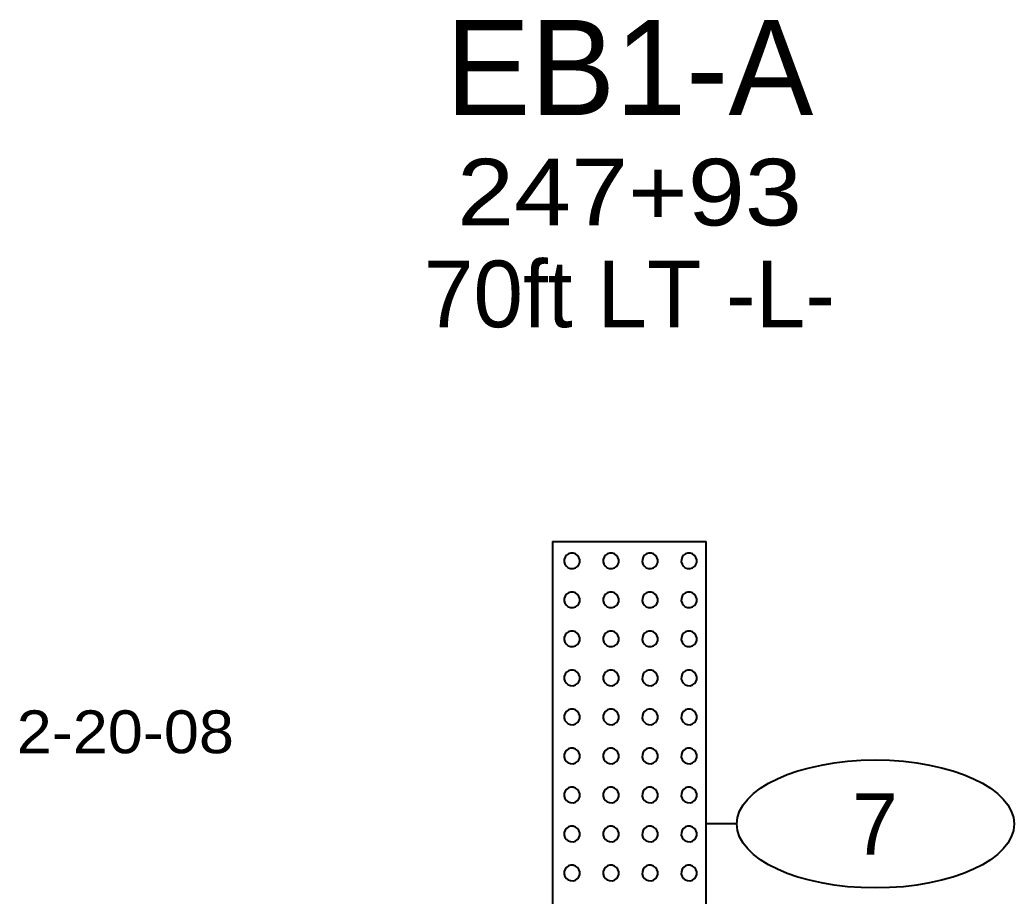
# Model space of a CAD drawing. Extents: x -76 to 974, y -1080 to -735.
# Drawn here: x -75.83 to -59.64, y -772.48 to -758.22 of the extents above; entities that cross this region are included whole.
import ezdxf
from ezdxf.enums import TextEntityAlignment as Align

# ---------------------------------------------------------------- set-up
doc = ezdxf.new("R2010")
doc.units = 0
doc.header["$LTSCALE"] = 0.36
doc.layers.add('27', color=7, linetype='Continuous', lineweight=40)

msp = doc.modelspace()

# ---------------------------------------------------------------- linework, layer by layer
at = {"layer": '27'}
for p, q in [((-67.154, -766.7053), (-67.154, -778.2053)), ((-67.154, -766.7053), (-64.654, -766.7053)), ((-64.654, -778.2053), (-64.654, -766.7053)), ((-64.154, -771.3053), (-64.654, -771.3053))]:
    msp.add_line(p, q, dxfattribs=at)
for points in [[(-66.7094, -767.0228), (-66.7109, -767.003), (-66.7231, -766.9654), (-66.7462, -766.9333), (-66.7781, -766.9099), (-66.8156, -766.8974), (-66.8552, -766.8971), (-66.8929, -766.9089), (-66.9252, -766.9317), (-66.9489, -766.9634), (-66.9617, -767.0008), (-66.9624, -767.0404), (-66.9509, -767.0782), (-66.9283, -767.1107), (-66.8969, -767.1347), (-66.8595, -767.1478), (-66.82, -767.1489), (-66.7821, -767.1377), (-66.7494, -767.1154), (-66.7251, -767.0841), (-66.7117, -767.0469)], [(-66.0744, -767.0228), (-66.0759, -767.003), (-66.0881, -766.9654), (-66.1112, -766.9333), (-66.1431, -766.9099), (-66.1806, -766.8974), (-66.2202, -766.8971), (-66.2579, -766.9089), (-66.2902, -766.9317), (-66.3139, -766.9634), (-66.3267, -767.0008), (-66.3274, -767.0404), (-66.3159, -767.0782), (-66.2933, -767.1107), (-66.2619, -767.1347), (-66.2245, -767.1478), (-66.185, -767.1489), (-66.1471, -767.1377), (-66.1144, -767.1154), (-66.0901, -767.0841), (-66.0767, -767.0469)], [(-65.4394, -767.0228), (-65.4409, -767.003), (-65.4531, -766.9654), (-65.4762, -766.9333), (-65.5081, -766.9099), (-65.5456, -766.8974), (-65.5852, -766.8971), (-65.6229, -766.9089), (-65.6552, -766.9317), (-65.6789, -766.9634), (-65.6917, -767.0008), (-65.6924, -767.0404), (-65.6809, -767.0782), (-65.6583, -767.1107), (-65.6269, -767.1347), (-65.5895, -767.1478), (-65.55, -767.1489), (-65.5121, -767.1377), (-65.4794, -767.1154), (-65.4551, -767.0841), (-65.4417, -767.0469)], [(-64.8044, -767.0228), (-64.8059, -767.003), (-64.8181, -766.9654), (-64.8412, -766.9333), (-64.8731, -766.9099), (-64.9106, -766.8974), (-64.9502, -766.8971), (-64.9879, -766.9089), (-65.0202, -766.9317), (-65.0439, -766.9634), (-65.0567, -767.0008), (-65.0574, -767.0404), (-65.0459, -767.0782), (-65.0233, -767.1107), (-64.9919, -767.1347), (-64.9545, -767.1478), (-64.915, -767.1489), (-64.8771, -767.1377), (-64.8444, -767.1154), (-64.8201, -767.0841), (-64.8067, -767.0469)], [(-66.7094, -767.6578), (-66.7109, -767.638), (-66.7231, -767.6004), (-66.7462, -767.5683), (-66.7781, -767.5449), (-66.8156, -767.5324), (-66.8552, -767.5321), (-66.8929, -767.5439), (-66.9252, -767.5667), (-66.9489, -767.5984), (-66.9617, -767.6358), (-66.9624, -767.6754), (-66.9509, -767.7132), (-66.9283, -767.7457), (-66.8969, -767.7697), (-66.8595, -767.7828), (-66.82, -767.7839), (-66.7821, -767.7727), (-66.7494, -767.7504), (-66.7251, -767.7191), (-66.7117, -767.6819)], [(-66.0744, -767.6578), (-66.0759, -767.638), (-66.0881, -767.6004), (-66.1112, -767.5683), (-66.1431, -767.5449), (-66.1806, -767.5324), (-66.2202, -767.5321), (-66.2579, -767.5439), (-66.2902, -767.5667), (-66.3139, -767.5984), (-66.3267, -767.6358), (-66.3274, -767.6754), (-66.3159, -767.7132), (-66.2933, -767.7457), (-66.2619, -767.7697), (-66.2245, -767.7828), (-66.185, -767.7839), (-66.1471, -767.7727), (-66.1144, -767.7504), (-66.0901, -767.7191), (-66.0767, -767.6819)], [(-65.4394, -767.6578), (-65.4409, -767.638), (-65.4531, -767.6004), (-65.4762, -767.5683), (-65.5081, -767.5449), (-65.5456, -767.5324), (-65.5852, -767.5321), (-65.6229, -767.5439), (-65.6552, -767.5667), (-65.6789, -767.5984), (-65.6917, -767.6358), (-65.6924, -767.6754), (-65.6809, -767.7132), (-65.6583, -767.7457), (-65.6269, -767.7697), (-65.5895, -767.7828), (-65.55, -767.7839), (-65.5121, -767.7727), (-65.4794, -767.7504), (-65.4551, -767.7191), (-65.4417, -767.6819)], [(-64.8044, -767.6578), (-64.8059, -767.638), (-64.8181, -767.6004), (-64.8412, -767.5683), (-64.8731, -767.5449), (-64.9106, -767.5324), (-64.9502, -767.5321), (-64.9879, -767.5439), (-65.0202, -767.5667), (-65.0439, -767.5984), (-65.0567, -767.6358), (-65.0574, -767.6754), (-65.0459, -767.7132), (-65.0233, -767.7457), (-64.9919, -767.7697), (-64.9545, -767.7828), (-64.915, -767.7839), (-64.8771, -767.7727), (-64.8444, -767.7504), (-64.8201, -767.7191), (-64.8067, -767.6819)], [(-66.7094, -768.2928), (-66.7109, -768.273), (-66.7231, -768.2354), (-66.7462, -768.2033), (-66.7781, -768.1799), (-66.8156, -768.1674), (-66.8552, -768.1671), (-66.8929, -768.1789), (-66.9252, -768.2017), (-66.9489, -768.2334), (-66.9617, -768.2708), (-66.9624, -768.3104), (-66.9509, -768.3482), (-66.9283, -768.3807), (-66.8969, -768.4047), (-66.8595, -768.4178), (-66.82, -768.4189), (-66.7821, -768.4077), (-66.7494, -768.3854), (-66.7251, -768.3541), (-66.7117, -768.3169)], [(-66.0744, -768.2928), (-66.0759, -768.273), (-66.0881, -768.2354), (-66.1112, -768.2033), (-66.1431, -768.1799), (-66.1806, -768.1674), (-66.2202, -768.1671), (-66.2579, -768.1789), (-66.2902, -768.2017), (-66.3139, -768.2334), (-66.3267, -768.2708), (-66.3274, -768.3104), (-66.3159, -768.3482), (-66.2933, -768.3807), (-66.2619, -768.4047), (-66.2245, -768.4178), (-66.185, -768.4189), (-66.1471, -768.4077), (-66.1144, -768.3854), (-66.0901, -768.3541), (-66.0767, -768.3169)], [(-65.4394, -768.2928), (-65.4409, -768.273), (-65.4531, -768.2354), (-65.4762, -768.2033), (-65.5081, -768.1799), (-65.5456, -768.1674), (-65.5852, -768.1671), (-65.6229, -768.1789), (-65.6552, -768.2017), (-65.6789, -768.2334), (-65.6917, -768.2708), (-65.6924, -768.3104), (-65.6809, -768.3482), (-65.6583, -768.3807), (-65.6269, -768.4047), (-65.5895, -768.4178), (-65.55, -768.4189), (-65.5121, -768.4077), (-65.4794, -768.3854), (-65.4551, -768.3541), (-65.4417, -768.3169)], [(-64.8044, -768.2928), (-64.8059, -768.273), (-64.8181, -768.2354), (-64.8412, -768.2033), (-64.8731, -768.1799), (-64.9106, -768.1674), (-64.9502, -768.1671), (-64.9879, -768.1789), (-65.0202, -768.2017), (-65.0439, -768.2334), (-65.0567, -768.2708), (-65.0574, -768.3104), (-65.0459, -768.3482), (-65.0233, -768.3807), (-64.9919, -768.4047), (-64.9545, -768.4178), (-64.915, -768.4189), (-64.8771, -768.4077), (-64.8444, -768.3854), (-64.8201, -768.3541), (-64.8067, -768.3169)], [(-66.7094, -768.9278), (-66.7109, -768.908), (-66.7231, -768.8704), (-66.7462, -768.8383), (-66.7781, -768.8149), (-66.8156, -768.8024), (-66.8552, -768.8021), (-66.8929, -768.8139), (-66.9252, -768.8367), (-66.9489, -768.8684), (-66.9617, -768.9058), (-66.9624, -768.9454), (-66.9509, -768.9832), (-66.9283, -769.0157), (-66.8969, -769.0397), (-66.8595, -769.0528), (-66.82, -769.0539), (-66.7821, -769.0427), (-66.7494, -769.0204), (-66.7251, -768.9891), (-66.7117, -768.9519)], [(-66.0744, -768.9278), (-66.0759, -768.908), (-66.0881, -768.8704), (-66.1112, -768.8383), (-66.1431, -768.8149), (-66.1806, -768.8024), (-66.2202, -768.8021), (-66.2579, -768.8139), (-66.2902, -768.8367), (-66.3139, -768.8684), (-66.3267, -768.9058), (-66.3274, -768.9454), (-66.3159, -768.9832), (-66.2933, -769.0157), (-66.2619, -769.0397), (-66.2245, -769.0528), (-66.185, -769.0539), (-66.1471, -769.0427), (-66.1144, -769.0204), (-66.0901, -768.9891), (-66.0767, -768.9519)], [(-65.4394, -768.9278), (-65.4409, -768.908), (-65.4531, -768.8704), (-65.4762, -768.8383), (-65.5081, -768.8149), (-65.5456, -768.8024), (-65.5852, -768.8021), (-65.6229, -768.8139), (-65.6552, -768.8367), (-65.6789, -768.8684), (-65.6917, -768.9058), (-65.6924, -768.9454), (-65.6809, -768.9832), (-65.6583, -769.0157), (-65.6269, -769.0397), (-65.5895, -769.0528), (-65.55, -769.0539), (-65.5121, -769.0427), (-65.4794, -769.0204), (-65.4551, -768.9891), (-65.4417, -768.9519)], [(-64.8044, -768.9278), (-64.8059, -768.908), (-64.8181, -768.8704), (-64.8412, -768.8383), (-64.8731, -768.8149), (-64.9106, -768.8024), (-64.9502, -768.8021), (-64.9879, -768.8139), (-65.0202, -768.8367), (-65.0439, -768.8684), (-65.0567, -768.9058), (-65.0574, -768.9454), (-65.0459, -768.9832), (-65.0233, -769.0157), (-64.9919, -769.0397), (-64.9545, -769.0528), (-64.915, -769.0539), (-64.8771, -769.0427), (-64.8444, -769.0204), (-64.8201, -768.9891), (-64.8067, -768.9519)], [(-66.7094, -769.5628), (-66.7109, -769.543), (-66.7231, -769.5054), (-66.7462, -769.4733), (-66.7781, -769.4499), (-66.8156, -769.4374), (-66.8552, -769.4371), (-66.8929, -769.4489), (-66.9252, -769.4717), (-66.9489, -769.5034), (-66.9617, -769.5408), (-66.9624, -769.5804), (-66.9509, -769.6182), (-66.9283, -769.6507), (-66.8969, -769.6747), (-66.8595, -769.6878), (-66.82, -769.6889), (-66.7821, -769.6777), (-66.7494, -769.6554), (-66.7251, -769.6241), (-66.7117, -769.5869)], [(-66.0744, -769.5628), (-66.0759, -769.543), (-66.0881, -769.5054), (-66.1112, -769.4733), (-66.1431, -769.4499), (-66.1806, -769.4374), (-66.2202, -769.4371), (-66.2579, -769.4489), (-66.2902, -769.4717), (-66.3139, -769.5034), (-66.3267, -769.5408), (-66.3274, -769.5804), (-66.3159, -769.6182), (-66.2933, -769.6507), (-66.2619, -769.6747), (-66.2245, -769.6878), (-66.185, -769.6889), (-66.1471, -769.6777), (-66.1144, -769.6554), (-66.0901, -769.6241), (-66.0767, -769.5869)], [(-65.4394, -769.5628), (-65.4409, -769.543), (-65.4531, -769.5054), (-65.4762, -769.4733), (-65.5081, -769.4499), (-65.5456, -769.4374), (-65.5852, -769.4371), (-65.6229, -769.4489), (-65.6552, -769.4717), (-65.6789, -769.5034), (-65.6917, -769.5408), (-65.6924, -769.5804), (-65.6809, -769.6182), (-65.6583, -769.6507), (-65.6269, -769.6747), (-65.5895, -769.6878), (-65.55, -769.6889), (-65.5121, -769.6777), (-65.4794, -769.6554), (-65.4551, -769.6241), (-65.4417, -769.5869)], [(-64.8044, -769.5628), (-64.8059, -769.543), (-64.8181, -769.5054), (-64.8412, -769.4733), (-64.8731, -769.4499), (-64.9106, -769.4374), (-64.9502, -769.4371), (-64.9879, -769.4489), (-65.0202, -769.4717), (-65.0439, -769.5034), (-65.0567, -769.5408), (-65.0574, -769.5804), (-65.0459, -769.6182), (-65.0233, -769.6507), (-64.9919, -769.6747), (-64.9545, -769.6878), (-64.915, -769.6889), (-64.8771, -769.6777), (-64.8444, -769.6554), (-64.8201, -769.6241), (-64.8067, -769.5869)], [(-66.7094, -770.1978), (-66.7109, -770.178), (-66.7231, -770.1404), (-66.7462, -770.1083), (-66.7781, -770.0849), (-66.8156, -770.0724), (-66.8552, -770.0721), (-66.8929, -770.0839), (-66.9252, -770.1067), (-66.9489, -770.1384), (-66.9617, -770.1758), (-66.9624, -770.2154), (-66.9509, -770.2532), (-66.9283, -770.2857), (-66.8969, -770.3097), (-66.8595, -770.3228), (-66.82, -770.3239), (-66.7821, -770.3127), (-66.7494, -770.2904), (-66.7251, -770.2591), (-66.7117, -770.2219)], [(-66.0744, -770.1978), (-66.0759, -770.178), (-66.0881, -770.1404), (-66.1112, -770.1083), (-66.1431, -770.0849), (-66.1806, -770.0724), (-66.2202, -770.0721), (-66.2579, -770.0839), (-66.2902, -770.1067), (-66.3139, -770.1384), (-66.3267, -770.1758), (-66.3274, -770.2154), (-66.3159, -770.2532), (-66.2933, -770.2857), (-66.2619, -770.3097), (-66.2245, -770.3228), (-66.185, -770.3239), (-66.1471, -770.3127), (-66.1144, -770.2904), (-66.0901, -770.2591), (-66.0767, -770.2219)], [(-65.4394, -770.1978), (-65.4409, -770.178), (-65.4531, -770.1404), (-65.4762, -770.1083), (-65.5081, -770.0849), (-65.5456, -770.0724), (-65.5852, -770.0721), (-65.6229, -770.0839), (-65.6552, -770.1067), (-65.6789, -770.1384), (-65.6917, -770.1758), (-65.6924, -770.2154), (-65.6809, -770.2532), (-65.6583, -770.2857), (-65.6269, -770.3097), (-65.5895, -770.3228), (-65.55, -770.3239), (-65.5121, -770.3127), (-65.4794, -770.2904), (-65.4551, -770.2591), (-65.4417, -770.2219)], [(-64.8044, -770.1978), (-64.8059, -770.178), (-64.8181, -770.1404), (-64.8412, -770.1083), (-64.8731, -770.0849), (-64.9106, -770.0724), (-64.9502, -770.0721), (-64.9879, -770.0839), (-65.0202, -770.1067), (-65.0439, -770.1384), (-65.0567, -770.1758), (-65.0574, -770.2154), (-65.0459, -770.2532), (-65.0233, -770.2857), (-64.9919, -770.3097), (-64.9545, -770.3228), (-64.915, -770.3239), (-64.8771, -770.3127), (-64.8444, -770.2904), (-64.8201, -770.2591), (-64.8067, -770.2219)], [(-66.7094, -770.8328), (-66.7109, -770.813), (-66.7231, -770.7754), (-66.7462, -770.7433), (-66.7781, -770.7199), (-66.8156, -770.7074), (-66.8552, -770.7071), (-66.8929, -770.7189), (-66.9252, -770.7417), (-66.9489, -770.7734), (-66.9617, -770.8108), (-66.9624, -770.8504), (-66.9509, -770.8882), (-66.9283, -770.9207), (-66.8969, -770.9447), (-66.8595, -770.9578), (-66.82, -770.9589), (-66.7821, -770.9477), (-66.7494, -770.9254), (-66.7251, -770.8941), (-66.7117, -770.8569)], [(-66.0744, -770.8328), (-66.0759, -770.813), (-66.0881, -770.7754), (-66.1112, -770.7433), (-66.1431, -770.7199), (-66.1806, -770.7074), (-66.2202, -770.7071), (-66.2579, -770.7189), (-66.2902, -770.7417), (-66.3139, -770.7734), (-66.3267, -770.8108), (-66.3274, -770.8504), (-66.3159, -770.8882), (-66.2933, -770.9207), (-66.2619, -770.9447), (-66.2245, -770.9578), (-66.185, -770.9589), (-66.1471, -770.9477), (-66.1144, -770.9254), (-66.0901, -770.8941), (-66.0767, -770.8569)], [(-65.4394, -770.8328), (-65.4409, -770.813), (-65.4531, -770.7754), (-65.4762, -770.7433), (-65.5081, -770.7199), (-65.5456, -770.7074), (-65.5852, -770.7071), (-65.6229, -770.7189), (-65.6552, -770.7417), (-65.6789, -770.7734), (-65.6917, -770.8108), (-65.6924, -770.8504), (-65.6809, -770.8882), (-65.6583, -770.9207), (-65.6269, -770.9447), (-65.5895, -770.9578), (-65.55, -770.9589), (-65.5121, -770.9477), (-65.4794, -770.9254), (-65.4551, -770.8941), (-65.4417, -770.8569)], [(-64.8044, -770.8328), (-64.8059, -770.813), (-64.8181, -770.7754), (-64.8412, -770.7433), (-64.8731, -770.7199), (-64.9106, -770.7074), (-64.9502, -770.7071), (-64.9879, -770.7189), (-65.0202, -770.7417), (-65.0439, -770.7734), (-65.0567, -770.8108), (-65.0574, -770.8504), (-65.0459, -770.8882), (-65.0233, -770.9207), (-64.9919, -770.9447), (-64.9545, -770.9578), (-64.915, -770.9589), (-64.8771, -770.9477), (-64.8444, -770.9254), (-64.8201, -770.8941), (-64.8067, -770.8569)], [(-66.7094, -771.4678), (-66.7109, -771.448), (-66.7231, -771.4104), (-66.7462, -771.3783), (-66.7781, -771.3549), (-66.8156, -771.3424), (-66.8552, -771.3421), (-66.8929, -771.3539), (-66.9252, -771.3767), (-66.9489, -771.4084), (-66.9617, -771.4458), (-66.9624, -771.4854), (-66.9509, -771.5232), (-66.9283, -771.5557), (-66.8969, -771.5797), (-66.8595, -771.5928), (-66.82, -771.5939), (-66.7821, -771.5827), (-66.7494, -771.5604), (-66.7251, -771.5291), (-66.7117, -771.4919)], [(-66.0744, -771.4678), (-66.0759, -771.448), (-66.0881, -771.4104), (-66.1112, -771.3783), (-66.1431, -771.3549), (-66.1806, -771.3424), (-66.2202, -771.3421), (-66.2579, -771.3539), (-66.2902, -771.3767), (-66.3139, -771.4084), (-66.3267, -771.4458), (-66.3274, -771.4854), (-66.3159, -771.5232), (-66.2933, -771.5557), (-66.2619, -771.5797), (-66.2245, -771.5928), (-66.185, -771.5939), (-66.1471, -771.5827), (-66.1144, -771.5604), (-66.0901, -771.5291), (-66.0767, -771.4919)], [(-65.4394, -771.4678), (-65.4409, -771.448), (-65.4531, -771.4104), (-65.4762, -771.3783), (-65.5081, -771.3549), (-65.5456, -771.3424), (-65.5852, -771.3421), (-65.6229, -771.3539), (-65.6552, -771.3767), (-65.6789, -771.4084), (-65.6917, -771.4458), (-65.6924, -771.4854), (-65.6809, -771.5232), (-65.6583, -771.5557), (-65.6269, -771.5797), (-65.5895, -771.5928), (-65.55, -771.5939), (-65.5121, -771.5827), (-65.4794, -771.5604), (-65.4551, -771.5291), (-65.4417, -771.4919)], [(-64.8044, -771.4678), (-64.8059, -771.448), (-64.8181, -771.4104), (-64.8412, -771.3783), (-64.8731, -771.3549), (-64.9106, -771.3424), (-64.9502, -771.3421), (-64.9879, -771.3539), (-65.0202, -771.3767), (-65.0439, -771.4084), (-65.0567, -771.4458), (-65.0574, -771.4854), (-65.0459, -771.5232), (-65.0233, -771.5557), (-64.9919, -771.5797), (-64.9545, -771.5928), (-64.915, -771.5939), (-64.8771, -771.5827), (-64.8444, -771.5604), (-64.8201, -771.5291), (-64.8067, -771.4919)], [(-66.7094, -772.1028), (-66.7109, -772.083), (-66.7231, -772.0454), (-66.7462, -772.0133), (-66.7781, -771.9899), (-66.8156, -771.9774), (-66.8552, -771.9771), (-66.8929, -771.9889), (-66.9252, -772.0117), (-66.9489, -772.0434), (-66.9617, -772.0808), (-66.9624, -772.1204), (-66.9509, -772.1582), (-66.9283, -772.1907), (-66.8969, -772.2147), (-66.8595, -772.2278), (-66.82, -772.2289), (-66.7821, -772.2177), (-66.7494, -772.1954), (-66.7251, -772.1641), (-66.7117, -772.1269)], [(-66.0744, -772.1028), (-66.0759, -772.083), (-66.0881, -772.0454), (-66.1112, -772.0133), (-66.1431, -771.9899), (-66.1806, -771.9774), (-66.2202, -771.9771), (-66.2579, -771.9889), (-66.2902, -772.0117), (-66.3139, -772.0434), (-66.3267, -772.0808), (-66.3274, -772.1204), (-66.3159, -772.1582), (-66.2933, -772.1907), (-66.2619, -772.2147), (-66.2245, -772.2278), (-66.185, -772.2289), (-66.1471, -772.2177), (-66.1144, -772.1954), (-66.0901, -772.1641), (-66.0767, -772.1269)], [(-65.4394, -772.1028), (-65.4409, -772.083), (-65.4531, -772.0454), (-65.4762, -772.0133), (-65.5081, -771.9899), (-65.5456, -771.9774), (-65.5852, -771.9771), (-65.6229, -771.9889), (-65.6552, -772.0117), (-65.6789, -772.0434), (-65.6917, -772.0808), (-65.6924, -772.1204), (-65.6809, -772.1582), (-65.6583, -772.1907), (-65.6269, -772.2147), (-65.5895, -772.2278), (-65.55, -772.2289), (-65.5121, -772.2177), (-65.4794, -772.1954), (-65.4551, -772.1641), (-65.4417, -772.1269)], [(-64.8044, -772.1028), (-64.8059, -772.083), (-64.8181, -772.0454), (-64.8412, -772.0133), (-64.8731, -771.9899), (-64.9106, -771.9774), (-64.9502, -771.9771), (-64.9879, -771.9889), (-65.0202, -772.0117), (-65.0439, -772.0434), (-65.0567, -772.0808), (-65.0574, -772.1204), (-65.0459, -772.1582), (-65.0233, -772.1907), (-64.9919, -772.2147), (-64.9545, -772.2278), (-64.915, -772.2289), (-64.8771, -772.2177), (-64.8444, -772.1954), (-64.8201, -772.1641), (-64.8067, -772.1269)]]:
    msp.add_lwpolyline(points, close=True, dxfattribs=at)
msp.add_ellipse((-61.8966, -771.3053), major_axis=(2.2574, 0), ratio=0.461538, dxfattribs=at)

# ---------------------------------------------------------------- texts
for s, height, p in [('EB1-A', 1.55, (-65.9025, -759.7658)), ('70ft LT -L-', 1.085, (-65.902, -763.2192)), ('7', 1, (-61.9039, -771.8052))]:
    msp.add_text(s, height=height, dxfattribs=at).set_placement(p, align=Align.CENTER)
for s, height, width, p in [('247+93', 1.085, 1.15, (-65.9015, -761.5622)), ('2-20-08', 0.6976, 1.1, (-74.1082, -770.1537))]:
    msp.add_text(s, height=height, dxfattribs=dict(at, width=width)).set_placement(p, align=Align.CENTER)

doc.saveas('drawing.dxf')
